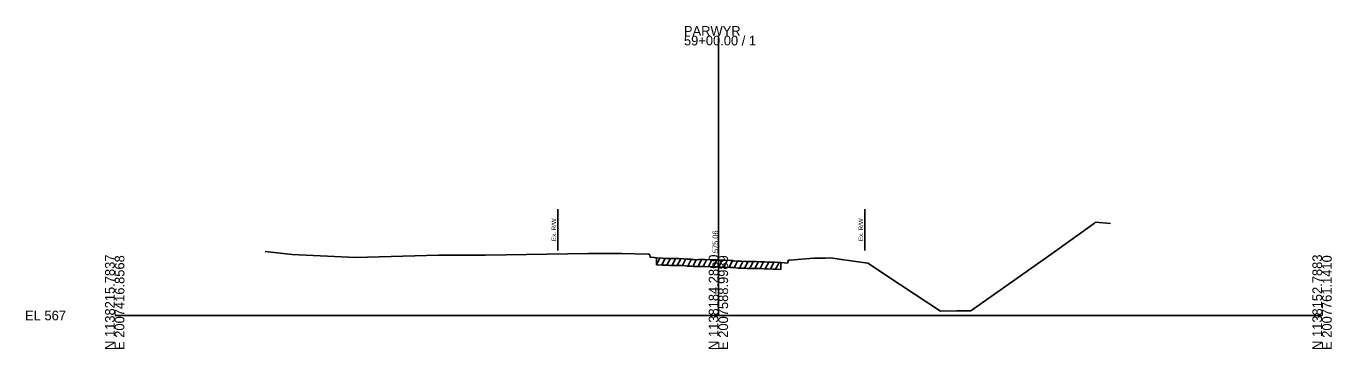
# Model space of a CAD drawing. Extents: x -2173 to 2007764, y -181 to 1138563.
# Drawn here: x 1017.4 to 1395.9, y 4490.3 to 4584 of the extents above; entities that cross this region are included whole.
import ezdxf

# ---------------------------------------------------------------- set-up
doc = ezdxf.new("R2010")
doc.units = 0
for name, color, linetype in [('Default', 7, 'Continuous'), ('RD_PD_Final_TrvlWay', 7, 'Continuous'), ('RD_PD_MedBWall', 7, 'Continuous'), ('RD_XS_ExPaveRet', 7, 'Continuous'), ('RD_XS_ExRW', 7, 'Continuous'), ('RD_XS_TX_Elev_EX', 7, 'Continuous')]:
    doc.layers.add(name, color=color, linetype=linetype)

msp = doc.modelspace()

# ---------------------------------------------------------------- linework, layer by layer
at = {"layer": 'RD_PD_Final_TrvlWay'}
msp.add_lwpolyline([(1086.71, 4518.58), (1094.49, 4517.71), (1112.93, 4516.85), (1136.95, 4517.5), (1150.56, 4517.54), (1180.34, 4517.95), (1184.92, 4518.01), (1187.52, 4518.02), (1190.12, 4517.95), (1197.7, 4517.82), (1198.1, 4517.77), (1198.33, 4516.9), (1199.46, 4516.81), (1200.19, 4516.74), (1201.84, 4516.64), (1203.02, 4516.57), (1204.06, 4516.52), (1205.9, 4516.52), (1206.55, 4516.49), (1207.94, 4516.46), (1209.04, 4516.36), (1209.97, 4516.3), (1210.31, 4516.27), (1210.88, 4516.25), (1211.68, 4516.18), (1212.34, 4516.22), (1212.76, 4516.22), (1213.14, 4516.23), (1214.13, 4516.2), (1216.07, 4516.15), (1216.5, 4516.14), (1218.1, 4516.12), (1218.99, 4516.07), (1220.14, 4516.01), (1221.48, 4515.95), (1222.17, 4515.91), (1222.49, 4515.88), (1223.79, 4515.78), (1224.49, 4515.73), (1224.82, 4515.72), (1225.85, 4515.69), (1226.46, 4515.68), (1228.27, 4515.65), (1228.95, 4515.64), (1230.3, 4515.61), (1231.43, 4515.55), (1232.33, 4515.5), (1233.92, 4515.44), (1234.37, 4515.43), (1236.21, 4515.39), (1238.09, 4515.23), (1238.38, 4516.05), (1238.78, 4516.08), (1245.79, 4516.61), (1249.16, 4516.67), (1250.72, 4516.69), (1253.13, 4516.35), (1261.46, 4515.16), (1270.85, 4508.85), (1282.45, 4501.24), (1287.18, 4501.37), (1291.27, 4501.37), (1314.89, 4518.01), (1327.1, 4526.81), (1327.46, 4527.06), (1331.78, 4526.72)], dxfattribs=at)
at = {"layer": 'RD_PD_MedBWall'}
for p, q in [((1218.1, 4500), (1218.1, 4581.17)), ((1043.1, 4500), (1218.1, 4500)), ((1218.1, 4500), (1393.1, 4500))]:
    msp.add_line(p, q, dxfattribs=at)
at = {"layer": 'RD_XS_ExPaveRet'}
for p, q in [((1200.19, 4514.74), (1200.19, 4516.74)), ((1200.19, 4514.74), (1201.16, 4516.68)), ((1201.69, 4514.65), (1202.67, 4516.59)), ((1203.19, 4514.56), (1204.17, 4516.52)), ((1204.69, 4514.52), (1205.69, 4516.52)), ((1206.19, 4514.51), (1207.18, 4516.48)), ((1207.69, 4514.46), (1208.66, 4516.4)), ((1209.19, 4514.35), (1210.16, 4516.28)), ((1210.69, 4514.26), (1211.66, 4516.19)), ((1212.19, 4514.21), (1213.2, 4516.23)), ((1213.69, 4514.21), (1214.68, 4516.18)), ((1215.19, 4514.17), (1216.18, 4516.15)), ((1216.69, 4514.14), (1217.69, 4516.13)), ((1218.19, 4514.12), (1219.16, 4516.06)), ((1219.69, 4514.03), (1220.67, 4515.99)), ((1221.19, 4513.96), (1222.17, 4515.91)), ((1200.19, 4514.74), (1201.84, 4514.64)), ((1200.19, 4514.74), (1200.19, 4514.74)), ((1201.84, 4514.64), (1203.02, 4514.57)), ((1203.02, 4514.57), (1204.06, 4514.52)), ((1204.06, 4514.52), (1205.9, 4514.52)), ((1205.9, 4514.52), (1206.55, 4514.49)), ((1206.55, 4514.49), (1207.94, 4514.46)), ((1207.94, 4514.46), (1209.04, 4514.36)), ((1209.04, 4514.36), (1209.97, 4514.3)), ((1209.97, 4514.3), (1210.31, 4514.27)), ((1210.31, 4514.27), (1210.88, 4514.25)), ((1210.88, 4514.25), (1211.68, 4514.18)), ((1211.68, 4514.18), (1212.34, 4514.22)), ((1212.34, 4514.22), (1212.76, 4514.22)), ((1212.76, 4514.22), (1213.14, 4514.23)), ((1213.14, 4514.23), (1214.13, 4514.2)), ((1214.13, 4514.2), (1216.07, 4514.15)), ((1216.07, 4514.15), (1216.5, 4514.14)), ((1216.5, 4514.14), (1218.1, 4514.12)), ((1218.1, 4514.12), (1218.99, 4514.07)), ((1218.99, 4514.07), (1220.14, 4514.01)), ((1220.14, 4514.01), (1221.48, 4513.95)), ((1221.48, 4513.95), (1222.17, 4513.91)), ((1222.17, 4513.91), (1222.49, 4513.88)), ((1222.49, 4513.88), (1223.79, 4513.78)), ((1222.69, 4513.87), (1223.66, 4515.79)), ((1223.79, 4513.78), (1224.49, 4513.73)), ((1224.19, 4513.75), (1225.17, 4515.71)), ((1224.49, 4513.73), (1224.82, 4513.72)), ((1224.82, 4513.72), (1225.85, 4513.69)), ((1225.69, 4513.7), (1226.68, 4515.68)), ((1225.85, 4513.69), (1226.46, 4513.68)), ((1226.46, 4513.68), (1228.27, 4513.65)), ((1227.19, 4513.67), (1228.19, 4515.65)), ((1228.27, 4513.65), (1228.95, 4513.64)), ((1228.69, 4513.64), (1229.68, 4515.62)), ((1228.95, 4513.64), (1230.3, 4513.61)), ((1230.19, 4513.61), (1231.17, 4515.56)), ((1230.3, 4513.61), (1231.43, 4513.55)), ((1231.43, 4513.55), (1232.33, 4513.5)), ((1231.69, 4513.53), (1232.67, 4515.49)), ((1232.33, 4513.5), (1233.92, 4513.44)), ((1233.19, 4513.47), (1234.18, 4515.44)), ((1233.92, 4513.44), (1234.37, 4513.43)), ((1234.37, 4513.43), (1236.21, 4513.39)), ((1234.69, 4513.42), (1235.68, 4515.4)), ((1236.21, 4515.39), (1236.21, 4513.39))]:
    msp.add_line(p, q, dxfattribs=at)
at = {"layer": 'RD_XS_ExRW'}
for p, q in [((1171.56, 4530.83), (1171.56, 4518.83)), ((1260.55, 4530.83), (1260.55, 4518.83))]:
    msp.add_line(p, q, dxfattribs=at)

# ---------------------------------------------------------------- texts
at = {"layer": 'Default'}
msp.add_text('-', height=0.0001, dxfattribs=at).set_placement((1043.1, 4500))
at = {"layer": 'RD_PD_MedBWall'}
for s, p in [('59+00.00 / 1', (1208.1, 4578.37)), ('PARWYR', (1208.1, 4581.17)), ('EL 567', (1017.1, 4498.6))]:
    msp.add_text(s, height=2.8, dxfattribs=at).set_placement(p)
for s, p in [('N 1138215.7837', (1043.1, 4490)), ('E 2007416.8568', (1045.9, 4490)), ('N 1138184.2860', (1218.1, 4490)), ('E 2007588.9989', (1220.9, 4490)), ('N 1138152.7883', (1393.1, 4490)), ('E 2007761.1410', (1395.9, 4490))]:
    msp.add_text(s, height=2.8, rotation=90, dxfattribs=at).set_placement(p)
at = {"layer": 'RD_XS_ExRW'}
for p in [(1171.06, 4521.6), (1260.05, 4521.6)]:
    msp.add_text('Ex. R/W ', height=1.3, rotation=90, dxfattribs=at).set_placement(p)
at = {"layer": 'RD_XS_TX_Elev_EX'}
msp.add_text('575.06', height=1.6, rotation=90, dxfattribs=at).set_placement((1218, 4518.12))

doc.saveas('drawing.dxf')
